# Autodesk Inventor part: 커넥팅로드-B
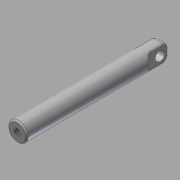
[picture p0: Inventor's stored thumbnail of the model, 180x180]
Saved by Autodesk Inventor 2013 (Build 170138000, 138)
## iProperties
Created: 2018-01
Part Number: 커넥팅로드-B
Material: 강철, 연강
Document SubType Name: Modeling
Designer: mduedu
Density: 1 g/cm^3
Author: mduedu
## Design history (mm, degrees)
sketch "스케치1"
  geometry: C1 r 3.5 at (0, 0); 1 further point
  constraints: 1 centre point, 1 coincident
  dimensions: "d0" = 7 diameter of C1
extrude "돌출1" new body sketch "스케치1" distance "d1" = 53; taper "d2" = 0 deg
node "작업 평면1"
sketch "스케치2"
  geometry: L1 (-3.5, 0)-(3.5, 0) reference; L2 (4, 4)-(4, 0); L3 (4, 0)-(-4, 0); L4 (-4, 0)-(-4, 4); A1 r 4 centre (0, 4) between (4, 4) and (-4, 4); 2 further points
  constraints: 6 end point, 2 perpendicular, 2 point on circle, 2 tangent, 1 centre point, 1 collinear, 1 midpoint, 1 vertical, 1 vertical alignment
  dimensions: "d4" = 8 diameter of A1; "d5" = 4 distance from line of A1.centre L1
extrude "돌출2" cut sketch "스케치2" stored distance "d6" = 53; taper "d7" = 0 deg
fillet "모깎기1" dims "d8" = 2
fillet "모깎기2" dims "d9" = 0.5
fillet "모깎기3" dims "d10" = 0.5
sketch "스케치3"
  geometry: C1 r 1.75 at (0, 3); 1 further point
  constraints: 1 centre point, 1 vertical alignment
  dimensions: "d11" = 3.5 diameter of C1; "d12" = 3 distance of point (0, 0) C1.centre
extrude "돌출3" cut sketch "스케치3" stored distance "d13" = 53; taper "d14" = 0 deg
chamfer "모따기1" distance "d15" = 0.5; stored, may be unused: second distance "d16" = 2, angle "d17" = 45 deg
sketch "스케치4"
  geometry: 1 further point
hole "구멍1" sketch "스케치4" at (0, 0) diameter "d18" = 2.459; stored, may be unused: countersink angle "d22" = 90 deg, drill point angle "d24" = 120 deg; dims "d19" = 6.9, "d20" = 4, "d21" = 2, "d23" = 8.4
node "솔리드1"
mirror "대칭1"
other parameters: "d3" = 2
